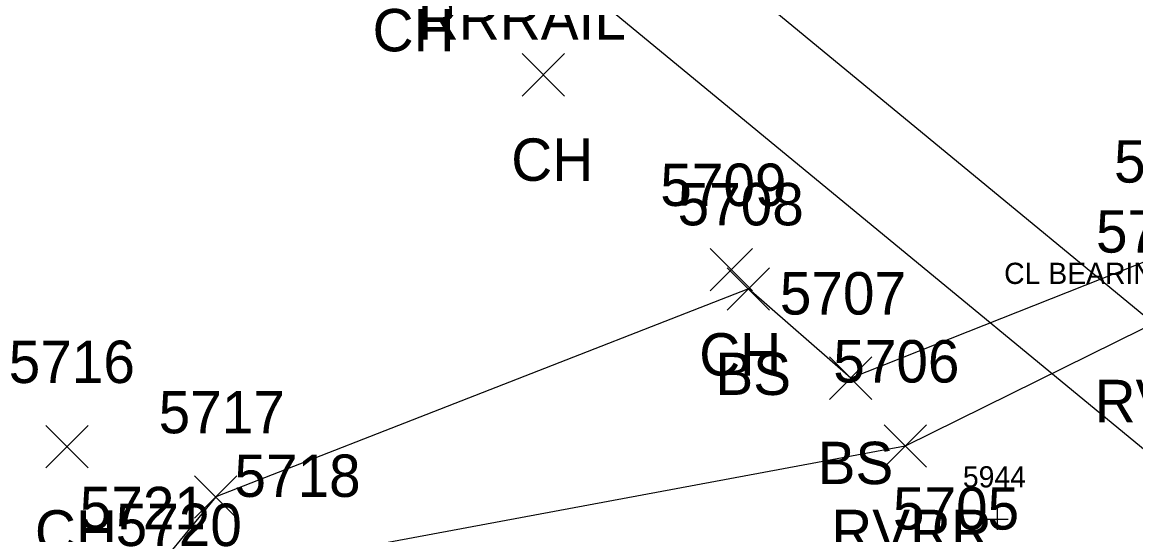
# Model space of a CAD drawing. Extents: x 1618146 to 1620418, y 640749 to 641927.
# Drawn here: x 1620030 to 1620082.5, y 641225.6 to 641249.8 of the extents above; entities that cross this region are included whole.
import ezdxf

# ---------------------------------------------------------------- set-up
doc = ezdxf.new("R2010")
doc.units = 0
for name, color, linetype in [('B_C', 7, 'Continuous'), ('B_I', 7, 'Continuous'), ('B_TIC', 7, 'Continuous'), ('D_I', 7, 'Continuous'), ('L_A', 7, 'Continuous'), ('L_I', 7, 'Continuous'), ('L_TIC', 7, 'Continuous'), ('LAWE', 7, 'Continuous'), ('LELB', 7, 'Continuous'), ('R_A', 7, 'Continuous'), ('RR', 7, 'Continuous')]:
    doc.layers.add(name, color=color, linetype=linetype)

msp = doc.modelspace()

# ---------------------------------------------------------------- linework, layer by layer
at = {"layer": 'B_TIC'}
msp.add_line((1620076.021, 641226.336), (1620076.097, 641226.336), dxfattribs=at)
for points in [[(1620076.018, 641225.836), (1620076.018, 641226.836)], [(1620075.518, 641226.336), (1620076.518, 641226.336)]]:
    msp.add_lwpolyline(points, dxfattribs=at)
at = {"layer": 'L_TIC'}
for points in [[(1620053.606, 641246.299), (1620055.606, 641248.299)], [(1620055.606, 641246.299), (1620053.606, 641248.299)], [(1620062.469, 641237.113), (1620064.469, 641239.113)], [(1620064.469, 641237.113), (1620062.469, 641239.113)], [(1620063.278, 641236.198), (1620065.278, 641238.198)], [(1620065.278, 641236.198), (1620063.278, 641238.198)], [(1620068.098, 641231.991), (1620070.098, 641233.991)], [(1620070.098, 641231.991), (1620068.098, 641233.991)], [(1620031.152, 641228.76), (1620033.152, 641230.76)], [(1620033.152, 641228.76), (1620031.152, 641230.76)], [(1620070.67, 641228.784), (1620072.67, 641230.784)], [(1620072.67, 641228.784), (1620070.67, 641230.784)], [(1620038.166, 641226.389), (1620040.166, 641228.389)], [(1620040.166, 641226.389), (1620038.166, 641228.389)]]:
    msp.add_lwpolyline(points, dxfattribs=at)
at = {"layer": 'LAWE'}
msp.add_lwpolyline([(1620126.924, 641247.392), (1620111.117, 641239.46), (1620109.41, 641236.163), (1620101.636, 641234.759), (1620084.088, 641235.913), (1620071.67, 641229.784), (1620042.737, 641224.388), (1620037.792, 641222.07), (1620025.57, 641215.03), (1620021.304, 641209.771), (1620016.061, 641211.085), (1620004.818, 641210.958), (1619989.454, 641201.04), (1619976.614, 641195.505), (1619948.377, 641191.059)], dxfattribs=at)
at = {"layer": 'LELB'}
msp.add_lwpolyline([(1620126.924, 641247.392), (1620111.61, 641247.659), (1620106.398, 641242.54), (1620098.527, 641237.323), (1620084.828, 641239.216), (1620069.098, 641232.991), (1620064.278, 641237.198), (1620039.166, 641227.389), (1620035.445, 641222.864), (1620023.476, 641219.069), (1620012.158, 641216.975), (1620003.405, 641213.467), (1619988.117, 641206.058), (1619975.419, 641196.769), (1619947.495, 641194.474)], dxfattribs=at)
at = {"layer": 'RR'}
for points in [[(1620192.149, 641127.788), (1620168.312, 641155.994), (1620153.359, 641171.838), (1620133.437, 641191.994), (1620110.111, 641213.081), (1620101.472, 641220.641), (1620055.356, 641258.678), (1620021.942, 641286.099), (1619984.199, 641317.184), (1619946.809, 641347.804), (1619927.299, 641363.881), (1619890.892, 641393.618), (1619862.546, 641416.891)], [(1620190.752, 641121.585), (1620164.758, 641152.663), (1620149.827, 641168.387), (1620129.761, 641188.505), (1620106.878, 641209.401), (1620098.404, 641216.876), (1620053.4, 641253.963), (1620018.83, 641282.236), (1619980.557, 641313.635), (1619944.224, 641343.671), (1619924.209, 641360.052), (1619888.22, 641389.605), (1619859.159, 641413.425)]]:
    msp.add_lwpolyline(points, dxfattribs=at)

# ---------------------------------------------------------------- texts
at = {"layer": 'B_C'}
msp.add_text('CL BEARING (CENTER OF BOLT)', height=1, dxfattribs=at).set_placement((1620076.334, 641237.435))
at = {"layer": 'B_I'}
msp.add_text('5944', height=1, dxfattribs=at).set_placement((1620074.388, 641227.836))
at = {"layer": 'D_I'}
msp.add_text('5705', height=2, dxfattribs=at).set_placement((1620071.091, 641225.847))
at = {"layer": 'L_A'}
for s, p in [('CH', (1620046.558, 641248.407)), ('CH', (1620053.095, 641242.299)), ('CH', (1620061.957, 641233.113)), ('BS', (1620062.719, 641232.198)), ('RVRR', (1620080.6, 641230.913)), ('BS', (1620067.539, 641227.991)), ('CH', (1620030.64, 641224.76)), ('RVRR', (1620068.182, 641224.784))]:
    msp.add_text(s, height=2, dxfattribs=at).set_placement(p)
at = {"layer": 'L_I'}
for s, p in [('5699', (1620081.514, 641242.216)), ('5709', (1620060.123, 641241.113)), ('5708', (1620060.939, 641240.198)), ('5700', (1620080.663, 641238.913)), ('5707', (1620065.759, 641235.991)), ('5716', (1620029.404, 641232.76)), ('5706', (1620068.277, 641232.784)), ('5717', (1620036.473, 641230.389)), ('5718', (1620040.045, 641227.388)), ('5721', (1620032.752, 641225.864)), ('5721', (1620032.752, 641225.864)), ('5720', (1620034.446, 641225.07)), ('5720', (1620034.446, 641225.07))]:
    msp.add_text(s, height=2, dxfattribs=at).set_placement(p)
at = {"layer": 'R_A'}
msp.add_text('RRRAIL', height=2, dxfattribs=at).set_placement((1620048.692, 641248.963))

doc.saveas('drawing.dxf')
